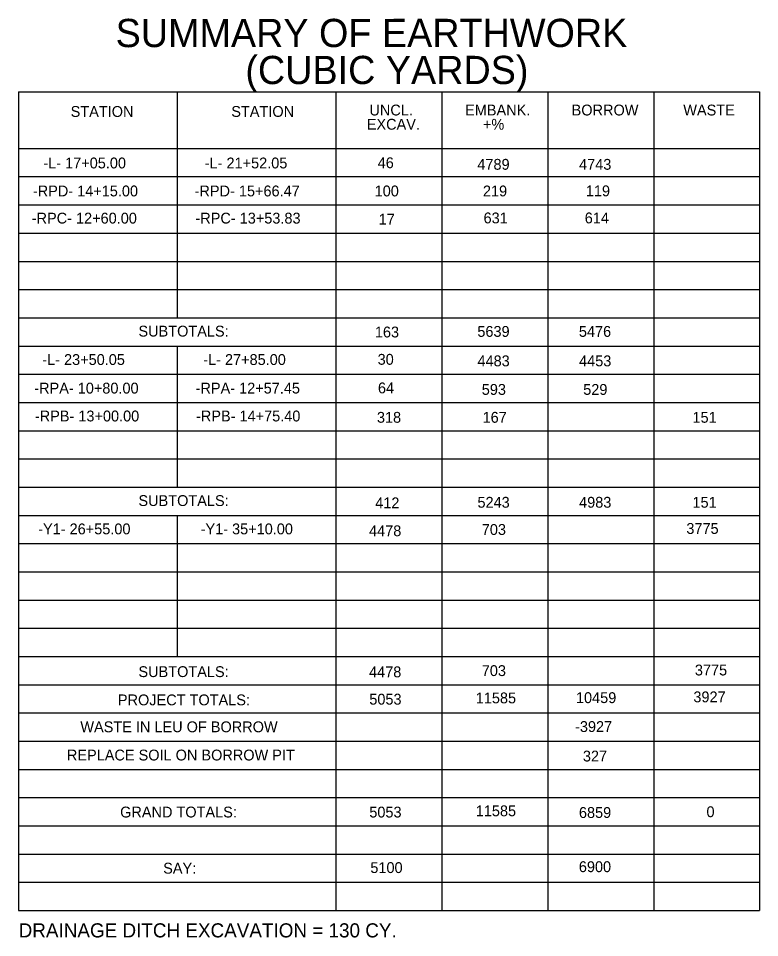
# Model space of a CAD drawing. Extents: x 2820318 to 2824860, y 680532 to 681838.
# Drawn here: x 2820317.5 to 2820645.8, y 681431.4 to 681838.5 of the extents above; entities that cross this region are included whole.
import ezdxf

# ---------------------------------------------------------------- set-up
doc = ezdxf.new("R2010")
doc.units = 0
for name, color, linetype in [('Sheet Summary Combination CELL', 7, 'Continuous'), ('Sheet Summary Combination Grid CELL', 7, 'Continuous'), ('Sheet Summary Earthwork CELL', 7, 'Continuous')]:
    doc.layers.add(name, color=color, linetype=linetype)

msp = doc.modelspace()

# ---------------------------------------------------------------- linework, layer by layer
at = {"layer": 'Sheet Summary Combination CELL'}
for p, q in [((2820411.87, 681805.81), (2820411.87, 681805.81)), ((2820418.12, 681805.71), (2820418.12, 681805.71)), ((2820427.17, 681805.91), (2820427.17, 681805.91)), ((2820432.77, 681805.81), (2820432.77, 681805.81))]:
    msp.add_line(p, q, dxfattribs=at)
at = {"layer": 'Sheet Summary Combination Grid CELL'}
for p, q in [((2820317.52, 681805.86), (2820645.77, 681805.86)), ((2820317.52, 681805.86), (2820317.52, 681443.36)), ((2820387.87, 681805.86), (2820387.87, 681705.86)), ((2820458.17, 681805.86), (2820458.17, 681443.36)), ((2820505.07, 681805.86), (2820505.07, 681443.36)), ((2820551.97, 681805.86), (2820551.97, 681443.36)), ((2820598.87, 681805.86), (2820598.87, 681443.36)), ((2820645.77, 681805.86), (2820645.77, 681443.36)), ((2820317.52, 681780.86), (2820645.77, 681780.86)), ((2820317.52, 681768.36), (2820645.77, 681768.36)), ((2820317.52, 681755.86), (2820645.77, 681755.86)), ((2820317.52, 681743.36), (2820645.77, 681743.36)), ((2820317.52, 681730.86), (2820645.77, 681730.86)), ((2820317.52, 681718.36), (2820645.77, 681718.36)), ((2820317.52, 681705.86), (2820645.77, 681705.86)), ((2820317.52, 681693.36), (2820645.77, 681693.36)), ((2820387.87, 681693.36), (2820387.87, 681630.86)), ((2820317.52, 681680.86), (2820645.77, 681680.86)), ((2820317.52, 681668.36), (2820645.77, 681668.36)), ((2820317.52, 681655.86), (2820645.77, 681655.86)), ((2820317.52, 681643.36), (2820645.77, 681643.36)), ((2820317.52, 681630.86), (2820645.77, 681630.86)), ((2820317.52, 681618.36), (2820645.77, 681618.36)), ((2820387.87, 681618.36), (2820387.87, 681555.86)), ((2820317.52, 681605.86), (2820645.77, 681605.86)), ((2820317.52, 681593.36), (2820645.77, 681593.36)), ((2820317.52, 681580.86), (2820645.77, 681580.86)), ((2820317.52, 681568.36), (2820645.77, 681568.36)), ((2820317.52, 681555.86), (2820645.77, 681555.86)), ((2820317.52, 681543.36), (2820645.77, 681543.36)), ((2820317.52, 681543.36), (2820645.77, 681543.36)), ((2820317.52, 681530.86), (2820645.77, 681530.86)), ((2820317.52, 681518.36), (2820645.77, 681518.36)), ((2820317.52, 681505.86), (2820645.77, 681505.86)), ((2820317.52, 681493.36), (2820645.77, 681493.36)), ((2820317.52, 681493.36), (2820645.77, 681493.36)), ((2820317.52, 681480.86), (2820645.77, 681480.86)), ((2820317.52, 681480.86), (2820645.77, 681480.86)), ((2820317.52, 681468.36), (2820645.77, 681468.36)), ((2820317.52, 681468.36), (2820645.77, 681468.36)), ((2820317.52, 681455.86), (2820645.77, 681455.86)), ((2820317.52, 681455.86), (2820645.77, 681455.86)), ((2820317.52, 681443.36), (2820645.77, 681443.36)), ((2820317.52, 681443.36), (2820645.77, 681443.36))]:
    msp.add_line(p, q, dxfattribs=at)

# ---------------------------------------------------------------- texts
at = {"layer": 'Sheet Summary Combination CELL'}
for s, p in [('SUMMARY OF EARTHWORK', (2820360.58, 681825.73)), ('(CUBIC YARDS)', (2820418.03, 681809.35))]:
    msp.add_text(s, height=12.5001, rotation=0.0119, dxfattribs=at).set_placement(p)
for s, p in [('STATION', (2820340.67, 681794.82)), ('STATION', (2820411.81, 681794.84)), ('UNCL.', (2820472.97, 681795.46)), ('EMBANK.', (2820515.35, 681795.46)), ('BORROW', (2820562.52, 681795.46)), ('WASTE', (2820611.97, 681795.46)), ('EXCAV.', (2820471.81, 681789.16)), ('+%', (2820523.23, 681789.16)), ('-L- 17+05.00', (2820328.59, 681772.02)), ('-L- 21+52.05', (2820400.05, 681772.02)), ('46', (2820476.63, 681772.11)), ('4789', (2820520.77, 681771.42)), ('4743', (2820565.83, 681771.42)), ('-RPD- 14+15.00', (2820323.94, 681759.63)), ('-RPD- 15+66.47', (2820395.56, 681759.63)), ('100', (2820475.29, 681759.63)), ('219', (2820523.24, 681759.63)), ('119', (2820568.81, 681759.68)), ('-RPC- 12+60.00', (2820323.43, 681747.59)), ('-RPC- 13+53.83', (2820395.92, 681747.59)), ('17', (2820477.08, 681747.13)), ('631', (2820523.52, 681747.68)), ('614', (2820568.33, 681747.68)), ('SUBTOTALS:', (2820370.69, 681697.55)), ('163', (2820475.39, 681697.16)), ('5639', (2820520.77, 681697.42)), ('5476', (2820565.74, 681697.42)), ('-L- 23+50.05', (2820328.11, 681684.97)), ('-L- 27+85.00', (2820399.38, 681684.97)), ('30', (2820476.61, 681685.06)), ('4483', (2820520.83, 681684.38)), ('4453', (2820565.83, 681684.38)), ('-RPA- 10+80.00', (2820324.55, 681672.32)), ('-RPA- 12+57.45', (2820396.01, 681672.32)), ('64', (2820476.75, 681672.41)), ('593', (2820522.73, 681671.73)), ('529', (2820567.66, 681671.73)), ('-RPB- 13+00.00', (2820324.82, 681659.97)), ('-RPB- 14+75.40', (2820396.19, 681659.97)), ('318', (2820476.3, 681659.38)), ('167', (2820523.09, 681659.38)), ('151', (2820616.04, 681659.38)), ('SUBTOTALS:', (2820370.69, 681622.51)), ('412', (2820475.55, 681621.5)), ('5243', (2820520.83, 681621.76)), ('4983', (2820565.83, 681621.76)), ('151', (2820616.04, 681621.76)), ('3775', (2820613.34, 681610.16)), ('-Y1- 26+55.00', (2820326.3, 681609.97)), ('-Y1- 35+10.00', (2820398.24, 681609.97)), ('4478', (2820472.82, 681609.15)), ('703', (2820522.73, 681609.71)), ('SUBTOTALS:', (2820370.69, 681546.76)), ('4478', (2820472.82, 681546.65)), ('703', (2820522.73, 681547.21)), ('3775', (2820617.11, 681547.47)), ('PROJECT TOTALS:', (2820361.59, 681534.25)), ('5053', (2820472.92, 681534.56)), ('11585', (2820520.07, 681535.12)), ('10459', (2820564.44, 681535.24)), ('3927', (2820616.44, 681535.58)), ('WASTE IN LEU OF BORROW', (2820344.96, 681522.32)), ('-3927', (2820564.04, 681522.44)), ('REPLACE SOIL ON BORROW PIT', (2820339.01, 681509.82)), ('327', (2820567.51, 681509.37)), ('GRAND TOTALS:', (2820362.57, 681484.58)), ('5053', (2820472.92, 681484.56)), ('11585', (2820520.07, 681485.12)), ('6859', (2820565.76, 681484.37)), ('0', (2820622.24, 681484.72)), ('SAY:', (2820381.64, 681459.72)), ('5100', (2820473.39, 681459.98)), ('6900', (2820565.72, 681460.38))]:
    msp.add_text(s, height=4.8, dxfattribs=at).set_placement(p)
at = {"layer": 'Sheet Summary Earthwork CELL'}
msp.add_text('DRAINAGE DITCH EXCAVATION = 130 CY.', height=6.25, dxfattribs=at).set_placement((2820317.64, 681431.46))

doc.saveas('drawing.dxf')
